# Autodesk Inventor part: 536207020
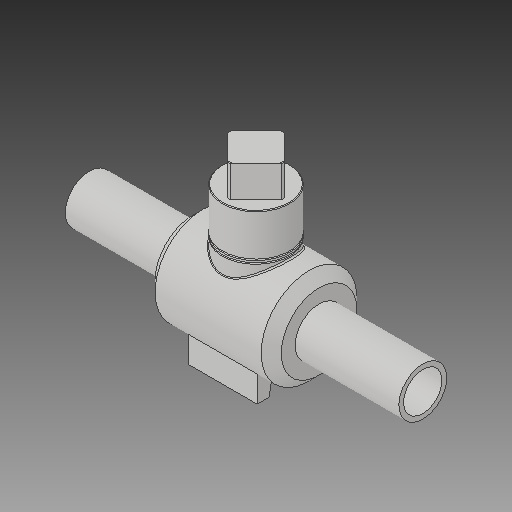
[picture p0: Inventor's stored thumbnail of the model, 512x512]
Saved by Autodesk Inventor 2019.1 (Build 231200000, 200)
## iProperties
Created: 2017-08
Part Number: 536207020
Material: Generic
Description: PLASSON PE BALL VALVE 2IPS''
Document SubType Name: Modeling
Designer: Кирилл
Density: 1 g/cm^3
Appearance: Default
Author: Кирилл
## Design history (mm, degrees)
derived "536207.ipt"
feature "Solid1::536207.ipt"
feature "Solid2::536207.ipt"
tag "TaggingFeature1"
body "Solid1"
other parameters: "d0" = 418, "d1" = 60.1, "d5" = 45.075, "d6" = 12.54, "d8" = 161, "d10" = 84, "d11" = 67.2, "d12" = 0.84, "d13" = 4, "d14" = 4, "d16" = 100 deg, "d19" = 76, "d20" = 86, "d21" = 0, "d22" = 0.84, "d26" = 6, "d28" = 0, "d29" = 1.68, "d32" = 83, "d33" = 53, "d37" = 0, "d_" = 60.1, "s_" = 6, "L_" = 418, "B_" = 86, "E_1" = 84, "H_" = 161, "H_1" = 76, "A_" = 83, "C_" = 53, "dp" = 48, "D_" = 48.3, "U_" = 26
